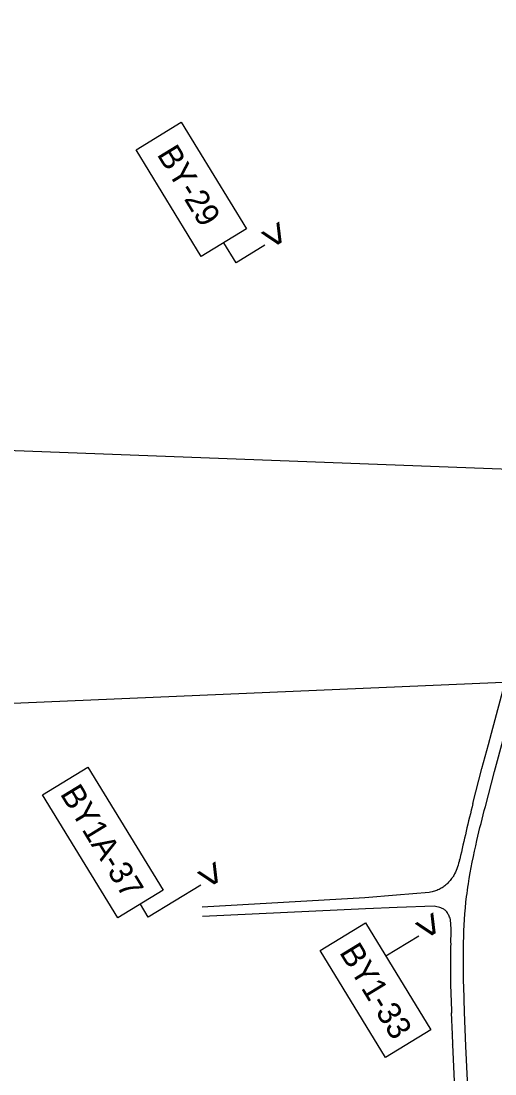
# Model space of a CAD drawing. Extents: x 1771071 to 1790027, y 804210 to 823391.
# Drawn here: x 1780215 to 1780972, y 812655 to 814333 of the extents above; entities that cross this region are included whole.
import ezdxf

# ---------------------------------------------------------------- set-up
doc = ezdxf.new("R2010")
doc.units = 0
for name, color, linetype in [('Default', 7, 'Continuous'), ('Exist Roads EOP', 7, 'Continuous'), ('Old_Level_57', 7, 'Continuous'), ('Prop Conc Shoulder Berm Gutter', 7, 'Continuous'), ('Proposed Right of Way Monument PSD Text', 7, 'Continuous'), ('Scratch_Level_1', 7, 'Continuous')]:
    doc.layers.add(name, color=color, linetype=linetype)

msp = doc.modelspace()

# ---------------------------------------------------------------- linework, layer by layer
at = {"layer": 'Default'}
for points in [[(1780471, 814171.9), (1780575.1, 814001.5), (1780503, 813957.4), (1780398.9, 814127.8)], [(1780322.1, 813143.5), (1780442, 812947.3), (1780369.8, 812903.2), (1780249.9, 813099.5)], [(1780764.8, 812895.4), (1780869, 812724.9), (1780796.8, 812680.9), (1780692.7, 812851.3)]]:
    msp.add_lwpolyline(points, close=True, dxfattribs=at)
for points in [[(1780604.3, 813975.4), (1780558.5, 813947.6), (1780539.1, 813979.4)], [(1780502.5, 812955.5), (1780418.5, 812904.3), (1780405.9, 812925.2)], [(1780850, 812874.3), (1780797.4, 812842.1)]]:
    msp.add_lwpolyline(points, dxfattribs=at)
at = {"layer": 'Exist Roads EOP'}
for p, q in [((1780914.8, 812994.6), (1780914.4, 812993.4)), ((1780915.2, 812995.4), (1780915.5, 812997)), ((1780901.5, 812881.8), (1780901.7, 812883.6)), ((1780901, 812863.3), (1780901.6, 812880.9))]:
    msp.add_line(p, q, dxfattribs=at)
for points in [[(1780936.5, 813085.9), (1780950.8, 813141.5), (1780961.2, 813179.6), (1780966.1, 813197.9), (1780979.9, 813249.1), (1780994.6, 813304.9), (1781009.5, 813358.1), (1781024.4, 813411.3), (1781038.5, 813462.6), (1781062.8, 813551.9), (1781067.3, 813567.7), (1781080.1, 813613.3), (1781092.2, 813657.3), (1781104.8, 813702.5), (1781118.5, 813751.7), (1781126.2, 813779.1), (1781132, 813799.5), (1781145.5, 813845.9), (1781158.8, 813893), (1781171.7, 813937.8), (1781184.2, 813979.1)], [(1780956.2, 813081), (1780970.9, 813136.6), (1780985.6, 813191.5), (1780999.7, 813243.3), (1781014.6, 813298.5), (1781029.6, 813352.4), (1781044.5, 813405.7), (1781057.7, 813456.2), (1781066.4, 813487.8), (1781074.8, 813518.5), (1781082.2, 813545.3), (1781087.1, 813562.9), (1781100.3, 813608.9), (1781112.3, 813651.8), (1781124.6, 813696.7), (1781138.2, 813745.7), (1781151.9, 813793.7), (1781165.4, 813840.5), (1781179, 813887.4), (1781192.6, 813931.8), (1781204.9, 813972.1)], [(1780866.7, 812944), (1780814.2, 812939.4), (1780763.9, 812935.5), (1780504.5, 812920.6)], [(1780874.3, 812921.8), (1780815.4, 812919.9), (1780764.8, 812917.8), (1780505.2, 812905.5)], [(1780948.2, 811760.1), (1780945.5, 811816.5), (1780942.9, 811873.6), (1780940, 811928.8), (1780937.6, 811986.1), (1780934.9, 812041.4), (1780932.6, 812095.1), (1780930.6, 812149.5), (1780927.9, 812207.5), (1780925.5, 812263.1), (1780922.8, 812320), (1780920.2, 812375.5), (1780917.4, 812431.8), (1780917.4, 812433.6), (1780914.7, 812480.7), (1780913.6, 812501.2), (1780912.9, 812516.8), (1780912.1, 812531.9), (1780910, 812586.7), (1780907, 812642.7), (1780904.5, 812701.5), (1780903.9, 812718.1), (1780902.4, 812751.8)], [(1780969.3, 811761.4), (1780966.9, 811817.7), (1780963.9, 811874.7), (1780961.1, 811929.9), (1780958.5, 811986.9), (1780956, 812042.2), (1780953.7, 812096.3), (1780951.1, 812151.1), (1780948.9, 812208.4), (1780946.4, 812263.7), (1780943.5, 812320), (1780940.9, 812376.8), (1780937.9, 812433.4), (1780938, 812434.5), (1780935.6, 812483.9), (1780932.9, 812535.4), (1780930.2, 812588.2), (1780927.6, 812644.1), (1780925.3, 812698.7), (1780923.2, 812753.2)]]:
    msp.add_lwpolyline(points, dxfattribs=at)
for centre, major_axis, ratio, start_param, end_param in [((1783377.8, 812427.3), (276.8, 2644.5), 0.949816, 1.419476, 1.453842), ((1782266.9, 812821.4), (-256.8, 1351.1), 0.993303, 1.353765, 1.434921)]:
    msp.add_ellipse(centre, major_axis=major_axis, ratio=ratio, start_param=start_param, end_param=end_param, dxfattribs=at)
for points in [[(1780506.7, 815662.6), (1780508.5, 815662.6), (1780522, 815663.3), (1780526.2, 815661.7), (1780532, 815652.7), (1780552.8, 815622.9), (1780582.5, 815582.6), (1780612.4, 815541.3), (1780642.6, 815499.8), (1780667.9, 815459.7), (1780694.7, 815417.2), (1780723.5, 815371.6), (1780749.4, 815330), (1780774.9, 815289.7), (1780802.5, 815246.6), (1780831, 815200.8), (1780854.3, 815163.2), (1780881.3, 815120.6), (1780909.6, 815075.5), (1780935.1, 815035.1), (1780962.6, 814991.4), (1780988.6, 814949.9), (1781014.4, 814909), (1781040.7, 814867.2), (1781067.8, 814824.4), (1781096, 814779.4), (1781125.2, 814733.4), (1781151.1, 814691.5), (1781176.1, 814651.7), (1781204.5, 814606.6), (1781230.2, 814566), (1781256.1, 814524.9), (1781282, 814483.3), (1781310.3, 814438.6), (1781335.3, 814399.1), (1781361.8, 814356.7), (1781382.8, 814322.4), (1781389.5, 814309.4), (1781392.1, 814297.9), (1781391.6, 814294.9)], [(1781302, 814247.2), (1781298.8, 814253.2), (1781270.8, 814297.7), (1781244, 814336.6), (1781214, 814378.2), (1781185.6, 814419.1), (1781159.3, 814463.2), (1781134.1, 814504.4), (1781108.9, 814545.7), (1781082.7, 814589.3), (1781057, 814632), (1781031.9, 814674), (1781005.9, 814717.4), (1780979.7, 814761.2), (1780955.2, 814801.9), (1780928.3, 814846.6), (1780901.1, 814891.7), (1780877.5, 814931.4), (1780851.5, 814974.5), (1780826.6, 815015.9), (1780800.4, 815059.6), (1780772.5, 815106.5), (1780747.5, 815148), (1780722.3, 815189.6), (1780707.5, 815214.7)], [(1780680.8, 815197.9), (1780694, 815175.8), (1780721, 815131.3), (1780745.9, 815089.2), (1780771.1, 815047.4), (1780798.4, 815002.1), (1780824, 814959.6), (1780848.3, 814918.8), (1780874.6, 814875.6), (1780902.1, 814829.2), (1780926, 814789.7), (1780952, 814746.6), (1780977.3, 814704.3), (1781002.8, 814661.4), (1781029.4, 814616.5), (1781054.5, 814575.4), (1781082.1, 814528.8), (1781105.7, 814488.2), (1781130.7, 814443.3), (1781155.8, 814398.5), (1781178.2, 814357.3), (1781202.4, 814313.6), (1781227.3, 814269.7), (1781240.7, 814246.1)], [(1780923.2, 812753.2), (1780921.4, 812808.1), (1780921.5, 812864.1), (1780926.3, 812937.4), (1780929.2, 812957.5), (1780942.8, 813026.9), (1780956.2, 813081)], [(1780914.4, 812993.4), (1780910.9, 812981.5), (1780905.7, 812970.7), (1780902.4, 812966), (1780897.6, 812960.3), (1780891.5, 812954.4), (1780885.8, 812950.5), (1780878.8, 812947.2), (1780871.2, 812944.9), (1780866.7, 812944)], [(1780901.7, 812883.6), (1780900.6, 812898.6), (1780899.9, 812903.1), (1780898.5, 812906.2), (1780895.7, 812911.2), (1780893.4, 812914.4), (1780888.7, 812917.9), (1780883.7, 812919.9), (1780874.3, 812921.8)]]:
    msp.add_spline(points, degree=3, dxfattribs=at)
at = {"layer": 'Prop Conc Shoulder Berm Gutter'}
for p, q in [((1781830.7, 813587), (1779981.1, 813656.1)), ((1781616.2, 813305.4), (1779771.4, 813226.6))]:
    msp.add_line(p, q, dxfattribs=at)
at = {"layer": 'Scratch_Level_1'}
for points in [[(1780903.9, 812719), (1780903, 812717.9)], [(1780904.5, 812701), (1780903.2, 812702)]]:
    msp.add_lwpolyline(points, dxfattribs=at)

# ---------------------------------------------------------------- texts
at = {"layer": 'Old_Level_57'}
for p in [(1780591.7, 813995.2), (1780489.9, 812975.3), (1780837.4, 812894.1)]:
    msp.add_text('>', height=47, rotation=301.4392, dxfattribs=at).set_placement(p)
at = {"layer": 'Proposed Right of Way Monument PSD Text'}
for s, p in [('BY-29', (1780431.4, 814120.4)), ('BY1A-37', (1780276.9, 813101.1)), ('BY1-33', (1780722.4, 812848.5))]:
    msp.add_text(s, height=37.32, rotation=301.4249, dxfattribs=at).set_placement(p)

doc.saveas('drawing.dxf')
